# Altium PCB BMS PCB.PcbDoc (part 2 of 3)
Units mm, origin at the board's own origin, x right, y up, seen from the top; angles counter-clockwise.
Board outline 105 x 42 mm, 6 copper layers (TOP, GND TOP, IN, GND IN, GND BOT, BOT), stack 1.517 mm thick; 241 components, 153 nets, 670 pads, 889 vias.
Unrouted connection lines stored in the file: 76.
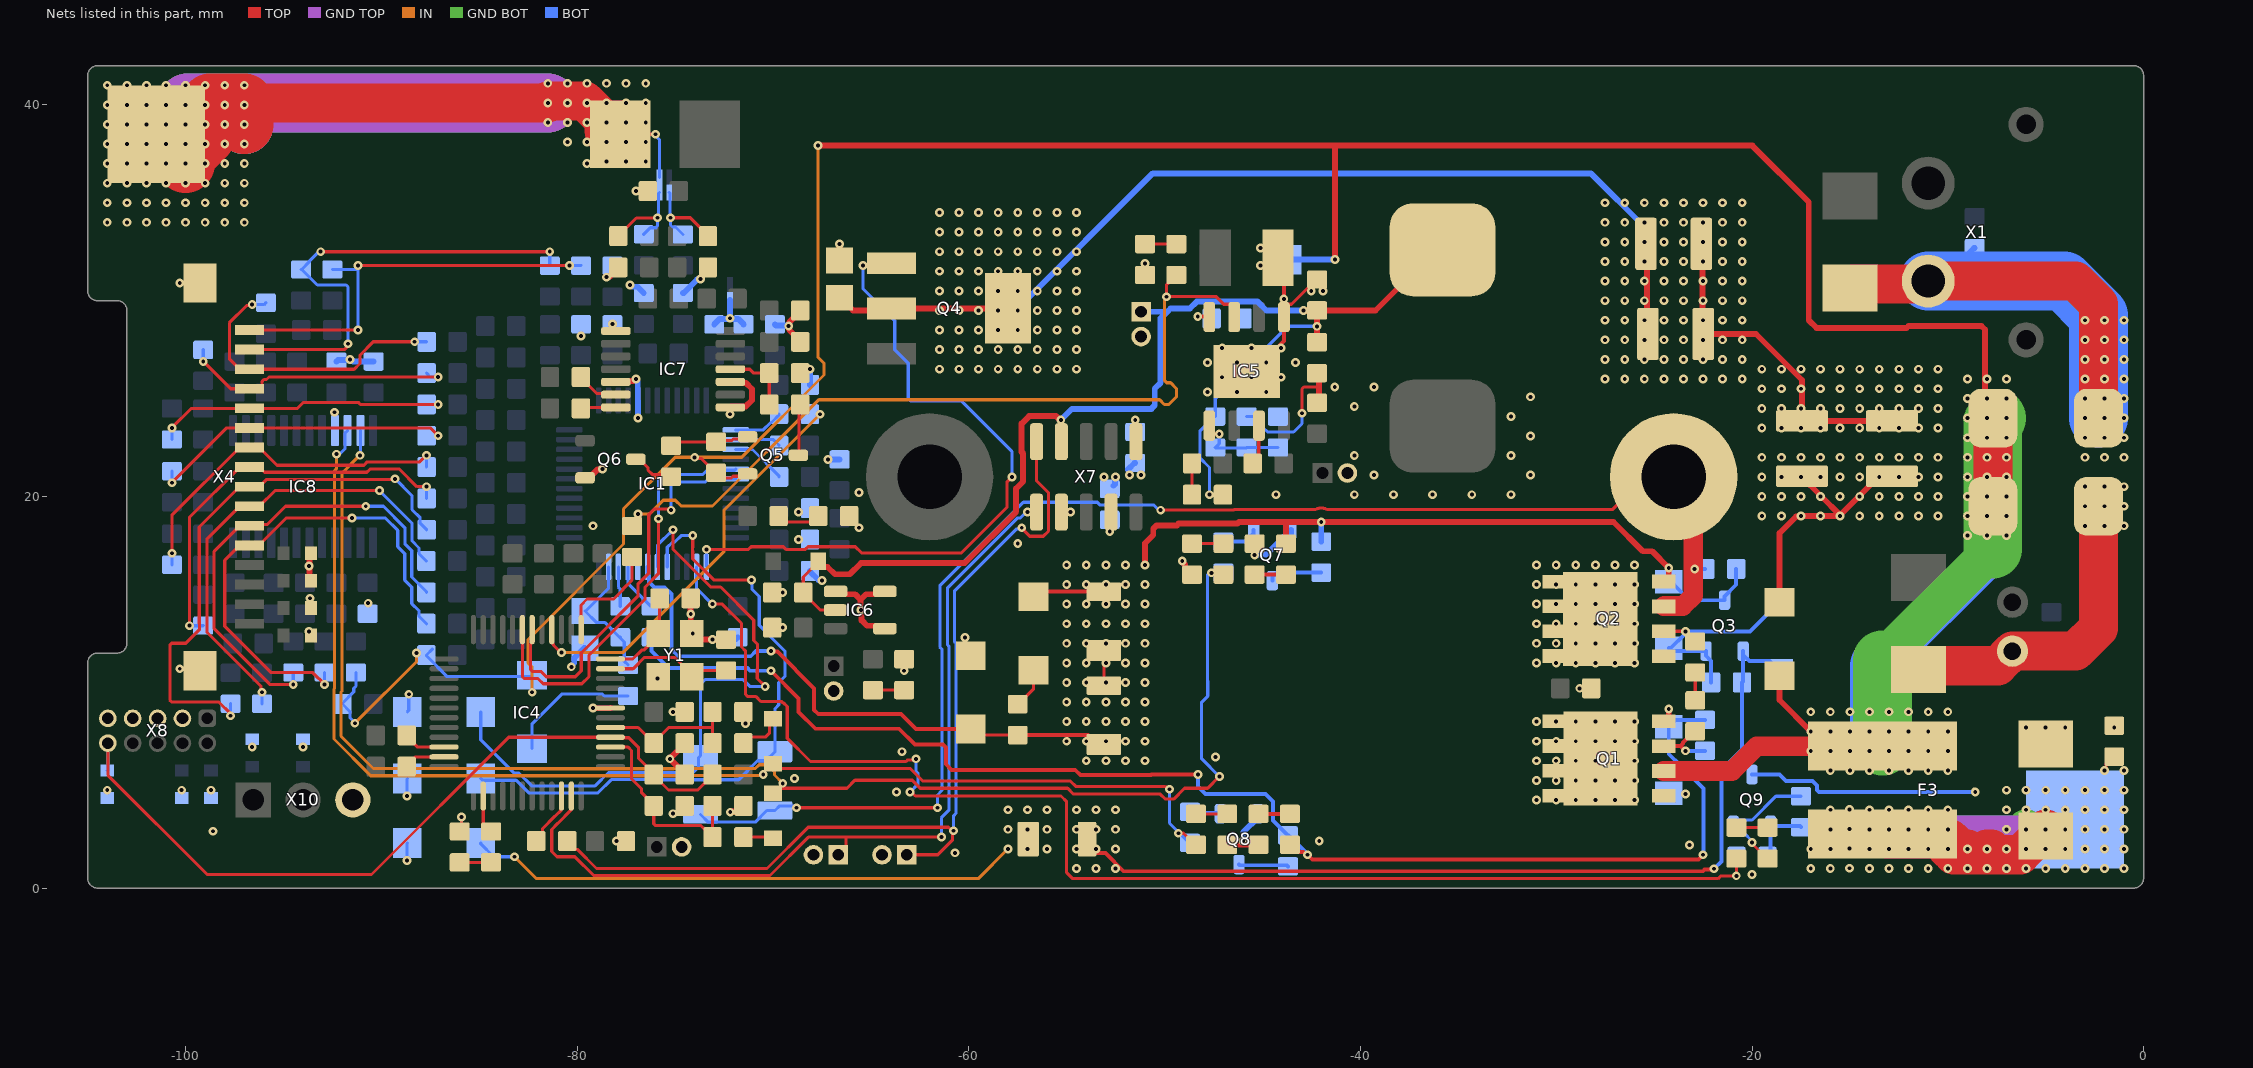
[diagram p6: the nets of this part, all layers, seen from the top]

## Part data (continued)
Y1: "Crystal oscillator 40MHz SMD 12pF 40R 10ppm", Frequency=40MHz, Manufacturer=JGHC

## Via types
v1: diameter 0.45, hole 0.2, TOP to BOT, tented both sides, 886 vias
v2: diameter 0.45/0.45/0.45/0.45/0.45/0 (per signal layer), hole 0.2, TOP to BOT, tented both sides, 3 vias

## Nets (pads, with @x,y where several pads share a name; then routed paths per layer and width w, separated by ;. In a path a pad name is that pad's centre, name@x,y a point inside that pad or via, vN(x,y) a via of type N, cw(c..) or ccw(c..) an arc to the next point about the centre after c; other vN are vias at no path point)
5V1: C41.2 C44.2 C45.2 D6.K IC6.2 L2.2 R63.2 R66.2 X7.4 X12.1 | length 67.2
  TOP w0.16: D6.K@-67.695,16.7 -67.695,16.65 -68.455,15.89 C45.2@-68.455,15.1 -68.455,15.06 -67.595,14.2 IC6.2@-66.8,14.2 ; v1(-47.705,20.09) R66.2@-47.02,20.09
  TOP w0.3: D6.K@-67.695,16.65 -67.445,16.4 -67.213,16.4 -66.838,16.025 -66.075,16.025 -65.5,16.6 -60.207,16.6 -57.58,19.227 -57.58,20.407 -57.225,20.762 -57.225,22.203 -57.3,22.278 -57.3,23.718 -56.918,24.1 -55.541,24.1 -55.354,23.913 v1@-55.313,23.913 ; v1(-55.3,23.9) -55.285,23.885 -55.285,22.815 X7.4@-55.27,22.8 ; v1(-42.9,29.5) C44.2@-42.21,29.5 ; C41.2@-42.21,27.621 C41.2@-42.21,27.88 v1(-42.21,28.69) C44.2@-42.21,29.5 ; L2.2@-36.918,33.698 L2.2@-35.81,32.59 -36.135,32.59 -39.225,29.5 C44.2@-42.21,29.5
  BOT w0.16: v1(-47.705,20.09) -47.71,20.095 -47.71,21.479 -48.2,21.969 -48.2,23.33 -47.45,24.08 R63.2@-47.41,24.08 -47.41,24.99 -43.71,28.69 v1(-42.21,28.69)
  BOT w0.3: v1(-55.3,23.9) -54.725,24.475 -50.676,24.475 -50.5,24.651 -50.5,25.513 -50.2,25.813 -50.2,29.1 -49.865,29.435 ; X12.1@-51.2,29.435 -49.865,29.435 ; v1(-42.9,29.5) -44.8,29.5 -45.25,29.95 -48.358,29.95 -48.708,29.6 -49.7,29.6 -49.865,29.435
ALRT: IC4.16 R31.2 | length 20.9
  TOP w0.16: IC4.16@-81.3,13.2 -81.279,13.179 -81.279,12.534 -81.215,12.47 -81.215,12.413 -80.827,12.025 v1(-80.8,12.025)
  IN w0.16: v1(-80.8,12.025) -77.669,12.025 -72.495,17.199 -72.495,19.305 v1(-67.6,24.2)
BAT: C7.1 C9.2 IC1.47 R19.2 | length 6.7
  BOT w0.16: IC1.47@-78.4,16.4 -78.4,15.306 -79.558,14.148 C9.2@-79.6,14.148 -79.024,13.572 -78.602,13.572 C7.1@-77.84,12.81 ; C7.1@-77.8,12.81 C7.1@-77.84,12.81 ; R19.2@-77.4,11.39 -77.6,11.59 -77.6,12.57 C7.1@-77.84,12.81
"BAT FG": IC7.4 R69.1 R72.2 | length 3.7
  TOP w0.16: IC7.4@-72.175,26.5 -71.185,26.5 -70.985,26.3 R72.2@-70.19,26.3 R69.1@-70.19,24.7
BAT+: C3.1 D7.A D13.A D16.A D29.A F1.1 F2.1 F3.2 Q1.S Q5.S R2.1 R10.1 R68.2 R79.1 R80.1 | length 195.1
  TOP w0.16: v1(-74,22) -73.945,21.945 -73.675,21.945 -72.94,21.21 R68.2@-72.9,21.21 -72.64,20.95 -72.12,20.95 -72.04,21.03 -71.42,21.03 Q5.S@-71.3,21.15
  TOP w0.2: Q1.S@-24.5,7.25 -23.66,7.25 ; v1(-23.39,7.01) -23.42,7.01 -23.66,7.25 ; C3.1@-22.9,8.01 -22.94,8.01 -23.519,7.431 -23.519,7.391 -23.66,7.25
  TOP w0.3: v1(-67.7,37.917) -41.3,37.917 ; v1(-41.3,32.1) -41.3,37.917 ; D13.A@-18.6,10.85 -18.6,9.6 v1(-17,8) ; v1(-8,25) -8.1,25.1 -8.1,28.524 -8.276,28.7 -12.012,28.7 -12.112,28.6 -16.7,28.6 -17.1,29 -17.1,35.034 -19.983,37.917 -41.3,37.917
  TOP w1: Q1.S@-24.5,5.98 -21.02,5.98 -19.75,7.25 F3.2@-13.335,7.25
  TOP w2: F2.1@-7.7,19.5 -7.7,23.8 F1.1@-7.5,24
  GND BOT w2: -13.335,11.665 -7.7,17.3
  GND BOT w3: -13.335,7.25 -13.335,11.665 ; -7.7,17.3 -7.7,23.8 -7.5,24
  IN w0.16: v1(-91.357,8.416) -88.2,11.573 v1(-88.2,12) ; v1(-82.3,10) -82.3,11.286 -82.505,11.491 -82.505,12.698 -77.634,17.569 -77.634,19.363 -74.997,22 v1(-74,22) -71.6,22 -67.395,26.205 -67.395,26.801 -67.7,27.106 v1(-67.7,37.917)
  BOT w0.16: v1(-91.357,8.416) -91.357,8.457 -91.609,8.709 -91.609,9.019 R79.1@-91.99,9.4 -91.99,9.448 -91.413,10.024 -91.413,10.201 -91.3,10.314 R80.1@-91.3,11.01 ; R10.1@-87.402,12.198 R10.1@-87.7,11.9 -87.7,11.86 -86.64,10.8 -82.375,10.8 D16.A@-82.3,10.875 v1(-82.3,10)
  BOT w0.2: v1(-23.39,7.01) R2.1@-22.4,7.01
  BOT w0.3: D29.A@-43.735,32.09 -43.725,32.1 v1(-41.3,32.1)
  BOT w2: -13.5,11.336 -7.7,17.136 -7.7,23.7 v1(-8,24)
  BOT w3: -13.5,7.415 -13.5,11.336
  other v1: -23.4,4.8 -16,6 -15,6 -14,6 -13,6 -12,6 -11,6 -10,6 -17,7 -16,7 -15,7 -14,7 -13,7 -12,7 -11,7 -10,7 -16,8 -15,8 -14,8 -13,8 -12,8 -11,8 -10,8 -17,9 -16,9 -15,9 -14,9 -13,9 -12,9 -11,9 -10,9 -9,18 -8,18 -7,18 -9,19 -8,19 -7,19 -9,20 -8,20 -7,20 -9,21 -8,21 -7,21 -9,22 -8,22 -7,22 -9,23 -8,23 -7,23 -9,24 -7,24 -9,25 -7,25 -9,26 -8,26 -7,26
"BAT+ C": C52.2 D32.K F3.1 X3.1 | length 36.1
  TOP w0.16: C52.2@-1.5,6.71 -1.532,6.71 -1.921,6.321 v1@-1.921,6.157 ; v1@-1.921,6.157 -1.921,6.079 v1(-2,6) -2,6.078 v1@-1.921,6.157
  TOP w2: F3.1@-13.335,2.75 -13.085,2.5 -9.864,2.5 -9.363,2 v1(-9,2) ; v1(-10,2) -9.7,1.7 -6.3,1.7 v1(-5,3) ; v1(-8,2) -7.768,2
  GND TOP w2: -13.3,2.7 -5.3,2.7 v1(-5,3)
  GND BOT w2: -13.3,2.7 -6.3,2.7 v1(-6,3)
  BOT w2: -13.3,2.7 -5,2.7 v1(-5,3)
  other v1: -17,1 -16,1 -14,1 -13,1 -12,1 -11,1 -10,1 -9,1 -8,1 -7,1 -6,1 -5,1 -4,1 -3,1 -2,1 -1,1 -15.019,1.013 -17,2 -16,2 -15.019,2.013 -14,2 -13,2 -12,2 -11,2 -7,2 -6,2 -5,2 -4,2 -3,2 -2,2 -1,2 -16,3 -14,3 -13,3 -12,3 -11,3 -10,3 -7,3 -4,3 -3,3 -2,3 -1,3 -15.019,3.013 -16,4 -14,4 -13,4 -12,4 -11,4 -10,4 -7,4 -6,4 -5,4 -4,4 -3,4 -2,4 -1,4 -15.019,4.013 -7,5 -6,5 -5,5 -4,5 -3,5 -2,5 -1,5 -1,6
BREG: IC1.37 Q4.B | length 36.1
  TOP w0.16: v1(-73.4,17.3) -71.248,17.3 -71.118,17.43 -69.479,17.43 -69.344,17.295 -68.346,17.295 -68.211,17.43 -65.791,17.43 -65.471,17.11 -60.389,17.11 -58.04,19.459 -58.04,20.76 v1(-57.8,21) ; v1(-65.4,31.8) -64.04,31.8 Q4.B@-63.94,31.9
  BOT w0.16: IC1.37@-73.4,16.4 v1(-73.4,17.3) ; v1(-65.4,31.8) -65.4,30.6 -63.78,28.98 -63.78,27.494 -63.095,26.809 -63.095,24.999 -62.986,24.89 -60.389,24.89 -57.8,22.301 v1(-57.8,21)
C1: R33.1 R92.1 X4.1 | length 21.5
  TOP w0.16: X4.1@-96.737,28.5 -93.6,28.5 v1(-91.2,28.5) ; v1(-91.2,31.8) v1(-80.4,31.8)
  BOT w0.16: R92.1@-92.5,31.59 -92.49,31.6 v1@-91.2,31.6 ; v1(-91.2,28.5) v1@-91.2,31.6 ; v1(-91.2,31.8) v1@-91.2,31.6 ; v1(-80.4,31.8) -79.81,31.8 R33.1@-79.8,31.79
C2: R30.1 R91.1 X4.2 | length 24.7
  TOP w0.16: X4.2@-96.737,27.5 -91.9,27.5 -91.7,27.7 v1(-91.7,27.8) ; v1(-93.1,32.5) v1(-81.4,32.5)
  BOT w0.16: R91.1@-94.06,31.59 -93.27,30.8 -91.799,30.8 -91.705,30.706 -91.705,27.805 v1(-91.7,27.8) ; v1(-93.1,32.5) -93.155,32.445 -93.245,32.445 -93.679,32.011 -93.679,31.979 R91.1@-94.068,31.59 ; R30.1@-81.4,31.79 v1(-81.4,32.5) ; R91.1@-94.068,31.59 R91.1@-94.1,31.59 R91.1@-94.068,31.59
C3: R28.1 R90.1 X4.3 | length 15.3
  TOP w0.16: v1(-96.6,29.8) -96.655,29.745 -96.889,29.745 -97.767,28.866 -97.767,27.03 -97.237,26.5 X4.3@-96.737,26.5 -91.814,26.5 -91.809,26.495 -91.391,26.495 -91.095,26.791 -91.095,27.219 -90.414,27.9 v1(-88.3,27.9)
  BOT w0.16: v1(-96.6,29.8) -95.99,29.8 R90.1@-95.9,29.89 ; v1(-88.3,27.9) R28.1@-87.69,27.9
C4: R26.1 R89.1 X4.4 | length 14.2
  TOP w0.16: v1(-99.1,26.9) -97.7,25.5 -96.264,25.5 -96.094,25.67 -96.094,25.876 -96,25.97 -95.871,25.97 -95.741,26.1 v1(-87.1,26.1)
  BOT w0.16: v1(-99.1,26.9) R89.1@-99.1,27.49 ; R26.1@-87.69,26.3 -87.49,26.1 v1(-87.1,26.1)
C5: R25.1 R88.1 X4.5 | length 14.8
  TOP w0.16: v1(-100.7,23.5) -99.7,24.5 -94.281,24.5 -93.977,24.805 -91.18,24.805 -91.075,24.7 -89.5,24.7 v1(-87.1,24.7)
  BOT w0.16: R88.1@-100.7,22.91 v1(-100.7,23.5)
C6: R24.1 R87.1 X4.6 | length 15.5
  TOP w0.16: v1(-100.7,20.7) -97.9,23.5 X4.6@-96.737,23.5 -87.5,23.5 v1(-87.1,23.1)
  BOT w0.16: v1(-100.7,20.7) R87.1@-100.7,21.29
C7: R23.1 R86.1 X4.7 | length 18.2
  TOP w0.16: v1(-100.7,17.1) -100.7,19.037 -97.237,22.5 -96.237,22.5 -95.332,21.595 -90.891,21.595 -90.721,21.765 -88.035,21.765 v1(-87.7,22.1)
  BOT w0.16: R86.1@-100.7,16.51 v1(-100.7,17.1) ; v1(-87.7,22.1) -87.7,21.51 R23.1@-87.69,21.5
C8: R22.1 R85.1 X4.8 | length 20.1
  TOP w0.16: v1(-99.8,13.4) -99.8,18.937 X4.8@-97.237,21.5 ; X4.8@-96.737,21.5 -96.237,21.5 -96.067,21.33 -96.067,21.329 -95.973,21.235 -90.742,21.235 -90.572,21.405 -89.091,21.405 -88.186,20.5 v1(-87.7,20.5)
  BOT w0.16: v1(-99.8,13.4) -99.11,13.4 R85.1@-99.1,13.41 ; v1(-87.7,20.5) -87.7,19.91 R22.1@-87.69,19.9
C9: R21.1 R84.1 X4.9 | length 28
  TOP w0.16: v1(-97.7,8.8) -97.7,8.9 -98.3,9.5 -100.706,9.5 -100.805,9.599 -100.805,12.401 -100.706,12.5 -99.986,12.5 -99.295,13.191 -99.295,13.5 -99.3,13.505 -99.3,18.437 X4.9@-97.067,20.67 ; X4.9@-96.737,20.5 -96.237,20.5 -95.862,20.875 -89.325,20.875 v1(-89.3,20.9)
  BOT w0.16: v1(-97.7,8.8) R84.1@-97.7,9.41 ; v1(-89.3,20.9) -88.44,20.04 -88.44,19.329 -88.023,18.912 -88.023,18.633 R21.1@-87.69,18.3
C10: R20.1 R83.1 X4.10 | length 24
  TOP w0.16: v1(-96.1,10) -96.142,10.042 -96.142,10.296 -98.9,13.054 -98.9,17.837 -97.237,19.5 -96.237,19.5 -95.437,20.3 v1(-90.1,20.3)
  BOT w0.16: R83.1@-96.1,9.41 v1(-96.1,10) ; v1(-90.1,20.3) -88.44,18.64 -88.44,17.729 -88.081,17.37 -88.081,17.081 R20.1@-87.7,16.7
C11: R18.1 R82.1 X4.11 | length 24.7
  TOP w0.16: v1(-94.5,10.4) -95.7,10.4 -98.54,13.24 -98.54,17.197 -97.237,18.5 X4.11@-96.737,18.5 -96.678,18.559 -95.841,18.559 -94.9,19.5 v1(-90.8,19.5)
  BOT w0.16: v1(-94.5,10.4) R82.1@-94.5,11.01 ; v1(-90.8,19.5) -89.891,19.5 -88.8,18.409 -88.8,17.58 -88.45,17.23 -88.45,15.89 -87.7,15.14 R18.1@-87.7,15.1
C12: R14.1 R81.1 X4.12 | length 25.7
  TOP w0.16: v1(-92.9,10.4) -93.5,11 -95.633,11 -98,13.367 -98,16.737 -97.237,17.5 -96.237,17.5 -96.067,17.67 -96.067,17.697 -94.864,18.9 v1(-91.5,18.9)
  BOT w0.16: v1(-92.9,10.4) R81.1@-92.9,11.01 ; v1(-91.5,18.9) -89.8,18.9 -89.167,18.267 -89.167,17.438 -88.81,17.081 -88.81,15.728 -88.45,15.368 -88.45,14.529 -88.081,14.16 -88.081,13.881 R14.1@-87.7,13.5
"CAN RX": IC4.47 X7.1 X15.1 | length 44
  TOP w0.16: IC4.47@-80.3,4.7 -80.321,4.679 -80.321,3.968 -80.984,3.305 -80.989,3.305 -81.3,2.994 -81.3,1.869 -81.031,1.6 -80.12,1.6 -79.16,0.64 -70.155,0.64 -68.195,2.6 -66.3,2.6 ; X15.1@-66.265,1.7 -66.265,2.565 -66.3,2.6 ; v1(-61.4,2.6) -66.3,2.6
  BOT w0.16: v1(-61.4,2.6) -61.4,3.586 -61.015,3.971 -61.015,12.357 -61.095,12.437 -61.095,15.315 -57.505,18.905 -57.363,18.905 -57.068,19.2 v1(-57,19.2)
"CAN TX": R38.2 X7.2 X16.1 | length 48.1
  TOP w0.16: R38.2@-80.51,2.4 -80.51,2.368 -80.121,1.979 -79.99,1.979 -79.011,1 -70.304,1 -68.199,3.105 -61.034,3.105 -60.854,2.925 v1(-60.776,2.925) -60.826,2.875 -60.826,2.46 -61.586,1.7 X16.1@-63.165,1.7 ; v1(-57.296,18.4) -57.15,18.4 -57.15,18.231 -56.889,17.97 -56.191,17.97 -55.93,18.231 -55.93,20.189 -56.54,20.799 X7.2@-56.54,22.8
  BOT w0.16: v1(-60.776,2.925) -60.776,3.701 -60.655,3.822 -60.655,12.506 -60.735,12.586 -60.735,15.166 -57.557,18.345 -57.351,18.345 v1(-57.296,18.4)
CFETOFF: IC1.29 IC4.19 | length 21.9
  TOP w0.16: IC4.19@-82.8,13.2 -82.8,10.8 -82.705,10.705 -82.008,10.705 -81.738,10.435 -79.764,10.435 -79.4,10.799 -79.4,11.889 -76.54,14.749 -76.54,15.371 -75.84,16.071 v1(-75.84,18.86)
  BOT w0.16: v1(-75.84,18.86) -75.84,20.966 -75.687,21.119 -73.584,21.119 -73.383,21.32 -72.589,21.32 -72.569,21.34 -71.96,21.34 IC1.29@-71.9,21.4
CHG: IC1.45 R6.1 | length 2.5
  BOT w0.16: IC1.45@-77.4,16.4 -77.4,15.55 -76.24,14.39 R6.1@-76.2,14.39
COUT: D38.A D40.A IC8.22 R100.1 | length 64.8
  TOP w0.16: v1(-70.5,5.795) -70.5,5.9 -70.05,6.35 D38.A@-70,6.35 -69.75,6.1 -69.114,6.1 -69.109,6.105 -68.691,6.105 -68.686,6.1 -62.977,6.1 -62.337,5.46 -54.806,5.46 -54.541,5.195 -49.973,5.195 -49.826,5.048 v1(-49.747,5.048) ; v1(-49.3,2.8) -49.038,2.8 -48.448,2.21 D40.A@-48.4,2.21
  IN w0.16: v1(-92.3,22.16) -92.3,21.409 -92.395,21.314 -92.395,10.191 -92.422,10.164 -92.422,7.612 -90.544,5.735 -74.912,5.735 -74.902,5.745 -70.55,5.745 v1(-70.5,5.795)
  BOT w0.16: v1(-92.3,22.16) -92.294,22.166 -92.134,22.166 -91.85,22.45 -91.85,23.245 IC8.22@-91.725,23.37 ; v1(-49.747,5.048) -49.747,3.317 -48.74,2.31 R100.1@-48.7,2.31
"COUT MCU": C69.2 IC4.5 R93.1 R95.2 | length 7.5
  TOP w0.16: IC4.5@-78.3,8.2 -76.89,8.2 -76.511,7.821 -76.479,7.821 C69.2@-76.09,7.432 ; C69.2@-76.09,7.4 C69.2@-76.09,7.432 ; R93.1@-73.09,7.4 -73.09,8.2 ; R95.2@-73.09,9 -73.09,8.2 ; C69.2@-76.09,7.432 -76.09,7.44 -75.33,8.2 -73.09,8.2
CP1: C7.2 IC1.46 | length 2.1
  BOT w0.16: IC1.46@-77.9,16.4 -77.9,15.372 -77.8,15.272 C7.2@-77.8,14.39
"DCDC EN": D18.A IC5.3 R44.1 | length 42.2
  TOP w0.16: R44.1@-77.2,18.49 -76.9,18.79 v1(-76.9,19.1) ; D18.A@-49.4,31.31 -49.432,31.31 -49.821,30.921 -49.821,30.889 -49.9,30.81 v1(-49.9,30.2) -49.883,30.217 -47.387,30.217 -46.984,29.814 -46.66,29.814 -46.5,29.655 -46.5,29.217 IC5.3@-46.445,29.162
  IN w0.16: v1(-76.9,19.1) -76.314,19.1 -75.609,19.805 -74.991,19.805 -74.695,19.509 -73.091,19.509 -67.66,24.94 -50.254,24.94 -50.014,24.7 -49.786,24.7 -49.395,25.091 -49.395,25.509 -49.691,25.805 -49.891,25.805 -50,25.914 -50,30.1 v1(-49.9,30.2)
"DCDC EN MCU": IC4.13 R44.2 | length 5.6
  TOP w0.16: IC4.13@-79.8,13.2 -79.8,14.46 -79.5,14.76 -78.129,14.76 -77.665,15.224 -77.665,15.265 -77.2,15.729 R44.2@-77.2,16.91
DFETOFF: IC1.30 IC4.18 | length 20.4
  TOP w0.16: IC4.18@-82.3,13.2 -82.3,12.555 -82.385,12.47 -82.385,11.159 -82.291,11.065 -81.859,11.065 -81.589,10.795 -80.091,10.795 -79.795,11.091 -79.795,12.003 -76.9,14.898 -76.9,15.52 -76.345,16.075 -76.345,19.069 -76.049,19.365 -75.631,19.365 -75.621,19.355 -75.255,19.355 v1(-75.2,19.3)
  BOT w0.16: v1(-75.2,19.3) -75.2,20.646 -75.106,20.74 -73.454,20.74 -73.294,20.9 IC1.30@-71.9,20.9
DOUT: D37.A D39.A IC8.23 R98.1 | length 76.7
  TOP w0.16: D37.A@-69.725,5.075 -69.95,4.85 D37.A@-70,4.85 -69.88,4.85 -69.63,5.1 -69.114,5.1 -69.109,5.095 -68.691,5.095 -68.686,5.1 -66.222,5.1 -65.817,5.505 -62.891,5.505 -62.486,5.1 -54.955,5.1 -54.655,4.8 -50.214,4.8 -49.957,4.543 -49.538,4.543 -48.981,5.1 -48.606,5.1 -48.601,5.095 -47.805,5.095 v1(-47.2,5.7) ; D37.A@-69.63,5.17 -69.5,5.3 v1(-69.5,5.35) ; v1(-47.6,16.1) -47.09,16.1 D39.A@-47,16.01
  IN w0.16: v1(-91.1,22.1) -92.005,21.195 -92.005,10.072 -92.062,10.015 -92.062,7.762 -90.4,6.1 -82.733,6.1 -82.728,6.095 -75.061,6.095 -75.051,6.105 -70.905,6.105 -70.709,6.3 -70.291,6.3 -69.923,5.932 -69.923,5.773 v1(-69.5,5.35)
  BOT w0.16: v1(-91.1,22.1) -91.075,22.125 IC8.23@-91.075,23.37 ; v1(-47.2,5.7) -48.106,6.606 -48.106,9.494 -47.795,9.805 -47.795,10.579 -47.811,10.594 -47.811,16.016 -47.717,16.11 R98.1@-47,16.11
"DOUT MCU": C70.2 IC4.3 R94.1 R96.2 | length 10.3
  TOP w0.16: IC4.3@-78.3,7.2 -77.4,7.2 -77.226,7.025 -77.226,5.575 -76.709,5.059 -76.709,4.859 -76.09,4.24 -76.09,3.284 -75.996,3.19 -73.68,3.19 -73.511,3.021 -73.479,3.021 -73.09,2.632 R94.1@-73.09,2.6 R96.2@-73.09,4.2
DSG: D11.K IC1.43 R7.1 R8.1 | length 30
  TOP w0.16: D11.K@-59.9,8.125 -59.585,7.81 R7.1@-57.5,7.81
  TOP w0.2: v1(-70.1,12.1) -70.079,12.079 -69.779,12.079 -67.9,10.2 -67.9,9.1 -67.688,8.888 -63.457,8.888 -62.695,8.125 D11.K@-59.9,8.125 ; R7.1@-57.5,7.81 -53.915,7.81 -53.605,7.5 v1(-53,7.5)
  BOT w0.2: IC1.43@-76.4,16.4 -76.4,16 -76.34,15.94 -76.34,15.642 -76.058,15.36 -75.538,15.36 -75.19,15.012 -75.19,12.191 -74.839,11.84 -71.138,11.84 -70.878,12.1 v1(-70.1,12.1)
  other v1: -54,6.5 -53,6.5 -52,6.5 -51,6.5 -55,7.5 -54,7.5 -52,7.5 -51,7.5 -55,8.5 -54,8.5 -53,8.5 -52,8.5 -51,8.5
"FB 5V1": C42.1 IC5.5 R63.1 R65.2 | length 4.8
  TOP w0.16: IC5.5@-47.715,23.618 -47.715,23.4 -47.5,23.185 v1(-47.21,23.185)
  BOT w0.16: v1(-47.21,23.185) -47.21,22.7 R63.1@-47.41,22.5 -47.393,22.482 -45.828,22.482 C42.1@-45.81,22.5 R65.2@-44.21,22.5
FUSE: D44.A IC1.38 R106.2 | length 69
  TOP w0.16: v1(-73.1,14.5) -72.592,14.5 -71.61,13.518 -71.61,12.31 -71.4,12.1 -71.4,9.884 -71.306,9.79 -70.887,9.79 -70.622,9.525 -69.554,9.525 -69.4,9.4 -69.388,9.389 -69.27,9.271 -69.27,7.651 -68.084,6.465 -66.035,6.465 -66.031,6.461 -63.2,6.461 -63.117,6.545 -62.755,6.545 v1(-62.7,6.6) ; v1(-63,4.9) -62.922,4.9 -62.727,4.705 -55.294,4.705 -55.005,4.416 -55.005,0.791 -54.694,0.48 -21.732,0.48 -21.587,0.625 v1(-20.8,0.625) D44.A@-20.8,1.51
  BOT w0.16: IC1.38@-73.9,16.4 -73.9,15.3 v1(-73.1,14.5) ; v1(-63,4.9) -62.6,5.3 -62.6,5.861 -62.7,5.961 v1(-62.7,6.6) ; v1(-20.8,0.625) -20.79,0.635 R106.2@-20.79,1.6
G_CHG: D7.K D41.A Q1.G R2.2 R6.2 R99.2 | length 72.8
  TOP w0.2: v1(-70.1,11.1) -68.69,9.69 -68.69,8.99 -67.837,8.137 -63.555,8.137 -62.743,7.325 -61.307,7.325 -61.165,7.183 -61.165,6.322 -60.883,6.04 -54.565,6.04 -54.3,5.775 -50.7,5.775 -50.675,5.8 v1(-48.3,5.8) ; D41.A@-43.6,2.21 -43.23,1.84 -42.908,1.84 -42.768,1.7 v1(-42.7,1.7) -42.698,1.7 -42.458,1.46 -22.742,1.46 -22.502,1.7 v1(-22.5,1.7)
  TOP w0.3: Q1.G@-24.5,8.52 -24.25,8.77 v1(-24.25,9.15)
  BOT w0.2: R6.2@-76.2,12.81 -76.2,12.1 -75.34,11.24 -71.308,11.24 -71.168,11.1 v1(-70.1,11.1) ; v1(-48.3,5.8) -48.3,5.179 -47.921,4.8 -44.837,4.8 -44.459,4.422 -44.459,3.449 R99.2@-43.7,2.69 ; R99.2@-43.66,2.69 -42.7,1.73 v1(-42.7,1.7) ; v1(-24.25,9.15) D7.K@-24.25,8.25 ; v1(-22.5,1.7) -22.475,1.725 -22.475,5.082 -23.644,6.251 -23.656,6.251 -24.25,6.845 D7.K@-24.25,8.25 ; R2.2@-22.4,8.59 -23.91,8.59 D7.K@-24.25,8.25
  BOT w0.3: v1@-24.291,9.15 v1(-24.25,9.15)
G_DSG: D8.K D9.A D42.A Q2.G Q3.D R3.1 R4.2 R97.2 | length 41.9
  TOP w0.2: D9.A@-56.7,14.875 -56.435,15.14 R4.2@-53.1,15.14 ; Q2.G@-24.51,15.655 -24.5,15.655 Q2.G@-24.25,15.905
  TOP w0.3: v1(-51,16.5) -51,17.61 -50.58,18.03 -50.58,18.349 -50.404,18.525 -49.368,18.525 -49.283,18.61 -46.288,18.61 -46.198,18.7 -43.8,18.7 ; D42.A@-43.8,17.59 -43.8,18.7 ; Q2.G@-24.25,15.905 v1(-24.25,16.35) -25.1,17.2 -25.574,17.2 -27.074,18.7 v1(-42,18.7) -43.8,18.7
  BOT w0.2: v1(-24.25,16.35) D8.K@-24.25,15.65 -24.15,15.65 -23.2,14.7 Q3.D@-21.4,14.7 -21.4,14.9 -20.81,15.49 R3.1@-20.81,16.3
  BOT w0.3: R97.2@-42,17.69 v1(-42,18.7)
  other v1: -55,14.5 -54,14.5 -53,14.5 -52,14.5 -51,14.5 -55,15.5 -54,15.5 -53,15.5 -52,15.5 -51,15.5 -55,16.5 -54,16.5 -53,16.5 -52,16.5
GND_BMS: C1.1 C2.1 C9.1 C12.1 C13.1 C14.1 C15.1 C20.1 C24.1 C25.1 C26.1 C27.1 C29.2 C30.1 C35.1 C36.1 C37.1 C43.1 C44.1 C45.1 C46.1 C47.1 C48.1 C50.2 C51.1 C52.1 C53.1 C54.1 C55.1 C68.1 C69.1 C70.1 C71.1 C72.1 D1.A D2.A D3.A D4.A D5.A D11.A D12.A D14.A D15.A D32.A D33.K D34.K D35.K D36.K IC1.17 IC4.7 IC5.1 IC5.9 IC6.1 IC6.4 IC6.6 IC7.1 IC7.3 IC7.8 IC7.12 IC8.21 NT1.1 NT3.2 Q6.S Q7.S Q8.S Q9.S R1.1 R34.1 R35.1 R53.2 R59.2 R64.1 R65.1 R67.2 R72.1 R77.1 R78.1 R95.1 R96.1 R101.2 R102.2 R103.2 R104.2 R105.2 R107.1 R108.2 R109.1 X4.CASE X7.3 X8.3 X8.5 X8.7 X8.9 X9.1 X10.3 X11.2 X12.2 X13.2 X14.2 X15.2 X16.2 Y1.2 Y1.4 | length 170.1
  TOP w0.16: v1(-100.3,11.2) -99.363,11.2 X4.CASE@-99.263,11.1 ; v1(-100.3,30.9) X4.CASE@-99.263,30.9 ; R59.2@-86,2.89 -85.9,2.99 -85.9,3.6 -85.915,3.615 v1(-85.915,3.633) ; R1.1@-77.8,38.5 v1(-76,38.5) ; R105.2@-66.11,19 -66.11,18.952 -65.6,18.442 v1(-65.6,18.4) ; v1(-63.3,11.1) R67.2@-63.3,11.69 ; v1(-60.2,12.8) -60.2,12.175 D11.A@-59.9,11.875 ; R53.2@-51,31.31 v1(-51,31.9) ; IC5.1@-43.905,29.162 -43.905,29.6 -43.69,29.814 -43.516,29.814 -42.25,31.08 C44.1@-42.21,31.08 ; v1(-20,2.329) -20,2.278 -19.232,1.51 R108.2@-19.2,1.51
  TOP w0.2: IC5.9@-45.81,26.39 -45.465,26.39 -43.905,27.95 IC5.1@-43.905,29.162 ; C43.1@-44.21,32.842 C43.1@-44.21,32.19 -43.905,31.885 IC5.1@-43.905,29.6
  TOP w0.3: D34.K@-93.6,15.7 -93.671,15.771 -93.671,16.421 v2(-93.7,16.45) -93.671,16.479 -93.671,17.029 D33.K@-93.6,17.1 ; Q6.S@-79.6,20.95 -79.391,20.95 -78.97,21.371 -78.729,21.371 v1(-78.7,21.4) ; v1(-79.2,9.2) -79.185,9.185 -78.315,9.185 IC4.7@-78.3,9.2 ; v1(-78.5,31.2) -78.471,31.229 -78.331,31.229 -77.9,31.66 C50.2@-77.9,31.7 ; IC7.12@-78.025,25.85 -77.975,25.9 -77.141,25.9 -77.041,26 v1(-77,26) ; C37.1@-74.51,5.8 -74.51,5.84 -75.27,6.6 -74.51,7.36 C69.1@-74.51,7.4 ; C72.1@-74.21,14.8 -74.205,14.795 -74.205,14.005 v1(-74.2,14) -74.2,13.1 v1(-74.1,13) -73.79,12.69 v1(-73.095,12.69) C71.1@-72.4,12.69 ; v1(-72.2,24.2) -72.2,24.525 IC7.1@-72.175,24.55 -72.125,24.6 -71.389,24.6 -71.075,24.914 -71.075,25.486 -71.389,25.8 -72.125,25.8 IC7.3@-72.175,25.85 ; v1(-72.185,3.875) -72.156,3.904 -71.806,3.904 R96.1@-71.51,4.2 ; C47.1@-68.61,27.9 -68.61,27.94 -69.171,28.501 -69.171,28.671 v1(-69.2,28.7) -69.171,28.729 -69.171,28.899 -68.61,29.46 C48.1@-68.61,29.5 ; IC6.1@-66.8,15.15 -66.655,15.005 -65.805,15.005 -65.529,14.729 ; C13.1@-66.6,32.048 v1(-66.6,32.9) ; IC6.4@-64.29,13.25 -64.435,13.395 -65.195,13.395 -65.471,13.671 -65.471,14.171 v1(-65.5,14.2) -65.529,14.229 -65.529,14.729 ; IC6.6@-64.29,15.15 -64.435,15.005 -65.252,15.005 -65.529,14.729 ; v1(-49.1,16.7) -49.1,16.659 -48.96,16.519 -48.96,16.036 -48.924,16 -48.61,16 R101.2@-48.6,16.01 ; R102.2@-46.8,2.21 -46.19,2.21 ; v1(-46,2.4) -46.19,2.21 ; v1(-45.4,17) R104.2@-45.4,17.59 ; R103.2@-45.2,2.21 -46.19,2.21
  TOP w2: v1@-97,40.1 v1(-81.5,40.1) ; v1@-81.5,40.2 -79.607,40.2 R1.1@-78.135,38.728
  TOP w3: X9.1@-100.5,37.5 v1(-101,38) X9.1@-101.5,38.5 -100.5,39.5 -99.343,39.5 -98.743,40.1 -97,40.1 v1(-97,40) v1(-97,39) ; v1(-100,37) -100,37.382 -98.982,38.4 ; R1.1@-78.135,38.728 -77.85,38.728 -77.8,38.678 R1.1@-77.8,38.5
  GND TOP w3: -101.5,38.5 v1(-100,40) -99.9,40.1 v1@-97,40.1 ; v1(-97,39) v1(-97,40) v1@-97,40.1 ; v1(-81.5,40.1) v1@-97,40.1
  GND BOT w3: -101.5,38.5 v1(-100,40) -99.9,40.1 v1@-97,40.1 ; v1(-97,39) v1(-97,40) v1@-97,40.1 ; v1(-81.5,40.1) v1@-97,40.1
  BOT w0.16: v1(-88.7,1.4) -88.7,2.275 D12.A@-88.675,2.3 ; v1(-88.7,4.7) -88.7,5.575 D15.A@-88.675,5.6 ; D14.A@-88.675,9 -88.6,9.075 v1(-88.6,9.9) ; v1(-76,38.5) -76,38.422 -75.8,38.222 NT1.1@-75.8,36.3 ; v1(-20,2.329) -20,2.4 -20.421,2.821 -20.744,2.821 -20.95,3.027 Q9.S@-20.95,3.2 -20.95,3.268 -20.744,3.474 -19.997,3.474 -18.781,4.69 R107.1@-17.5,4.69
  BOT w0.3: C68.1@-92.3,26.89 -92.219,26.971 -91.629,26.971 v1(-91.6,27) -91.559,27 -91.449,26.89 R109.1@-90.4,26.89 ; v1(-80.3,11.3) -80.3,11.341 -80.148,11.492 -80.148,11.746 -79.642,12.252 C9.1@-79.6,12.252 ; v1(-77.3,30.8) -77.259,30.8 -77.169,30.71 -76.92,30.71 C29.2@-76.6,30.39 ; v1(-77,26) -77,25.959 -76.91,25.869 -76.91,24.91 IC1.17@-76.9,24.9 ; v1(-76.9,24) IC1.17@-76.9,24.9 ; C30.1@-74.6,30.39 -74.56,30.39 -73.878,31.071 -73.729,31.071 v1(-73.7,31.1) ; v1(-73.095,12.69) -73.066,12.719 -71.891,12.719 C12.1@-71.8,12.81 ; C20.1@-73,28.79 -72.719,29.071 -72.229,29.071 v1(-72.2,29.1) ; NT3.2@-72.2,30.025 v1(-72.2,29.1) ; C53.1@-71.5,28.79 -71.781,29.071 -72.171,29.071 v1(-72.2,29.1) ; C54.1@-69.9,28.79 -69.839,28.729 -69.229,28.729 v1(-69.2,28.7) ; C15.1@-68.11,16.2 -68.11,16.16 -67.679,15.729 -67.529,15.729 v1(-67.5,15.7) ; C24.1@-68.11,25.7 -68.105,25.705 -68.105,26.495 v1(-68.1,26.5) ; v1(-67.19,21.89) R34.1@-66.6,21.89 ; C1.1@-52.605,20.545 -52.529,20.621 -52.529,20.971 v1(-52.5,21) ; C2.1@-51.86,21.39 -51.54,21.71 C2.1@-51.5,21.71 ; v1(-46,2.4) -45.971,2.429 -45.971,2.87 -45.25,3.591 Q8.S@-45.25,3.8 ; v1(-45.4,17) -45.371,17.029 -44.821,17.029 -43.9,17.95 -43.691,17.95 -43.55,18.091 Q7.S@-43.55,18.3
  BOT w3: -101.5,38.5 v1(-100,40) -99.9,40.1 v1@-97,40.1 ; v1(-97,40) v1@-97,40.1 ; v1(-81.5,40.1) v1@-97,40.1
  other v1: -20,0.7 -60.7,1.8 -23.2,2.2 -78,2.4 -42.1,2.4 -98.6,2.9 -75.1,3.8 -63.7,4.9 -104,5 -100.2,5 -98.7,5 -68.9,5.6 -75.27,6.6 -47.4,6.7 -63.41,6.966 -96.6,7.2 -94,7.2 -6,8.2 -5,8.2 -4,8.2 -1.5,8.2 -71.4,8.4 -75.1,9 -28.8,10.2 -75.9,10.7 -69.5,13.3 -90.675,14.55 -69.5,15.1 -57.5,17.6 -68.7,17.8 -79.2,18.5 -68.7,19.2 -54.8,19.2 -44.31,20.09 -40.31,20.09 -38.31,20.09 -36.31,20.09 -34.31,20.09 -32.31,20.09 -65.6,20.2 -53.1,21 -39.31,21.09 -31.31,21.09 -51.8,21.1 -51.2,21.1 -40.31,22.09 -32.31,22.09 -31.31,23.09 -32.31,24.09 -92.4,24.3 -40.31,24.59 -31.31,25.09 -47.81,25.34 -46.31,25.34 -44.81,25.34 -41.31,25.59 -39.31,25.59 -47.06,26.09 -45.56,26.09 -44.06,26.09 -47.81,26.84 -46.31,26.84 -44.81,26.84 -43.31,26.84 -47.06,27.59 -45.56,27.59 -44.06,27.59 -79.8,28.2 -78.2,28.8 -43.91,30.09 -42.51,30.49 -41.91,30.49 -45.11,31.79 -45.11,32.69 -104,34 -103,34 -102,34 -101,34 -100,34 -99,34 -98,34 -97,34 -104,35 -103,35 -102,35 -101,35 -100,35 -99,35 -98,35 -97,35 -77,35.6 -104,36 -103,36 -102,36 -101,36 -100,36 -99,36 -98,36 -97,36 -104,37 -103,37 -102,37 -101,37 -99,37 -98,37 -97,37 -79.5,37 -78.5,37.1 -77.5,37.1 -76.5,37.1 -104,38 -103,38 -102,38 -100,38 -99,38 -98,38 -97,38 -80.5,38.1 -79.5,38.1 -78.5,38.1 -77.5,38.1 -76.5,38.1 -104,39 -103,39 -102,39 -101,39 -100,39 -99,39 -98,39 -81.5,39.1 -80.5,39.1 -79.5,39.1 -78.5,39.1 -77.5,39.1 -76.5,39.1 -104,40 -103,40 -102,40 -101,40 -99,40 -98,40 -80.5,40.1 -79.5,40.1 -78.5,40.1 -77.5,40.1 -76.5,40.1 -104,41 -103,41 -102,41 -101,41 -100,41 -99,41 -98,41 -97,41 -81.5,41.1 -80.5,41.1 -79.5,41.1 -78.5,41.1 -77.5,41.1 -76.5,41.1
  other v2: -93.7,13.1 -93.65,14.8
HFXIN: C71.2 IC4.11 Y1.1 | length 6.7
  TOP w0.16: IC4.11@-78.3,11.2 -77.146,11.2 -76.566,11.78 -75.03,11.78 -74.15,10.9 Y1.1@-74.15,10.8 -74.1,10.85 -73.84,11.11 C71.2@-72.4,11.11
HFXOUT: C72.2 IC4.12 Y1.3 | length 4.9
  TOP w0.16: IC4.12@-78.3,11.7 -77.155,11.7 -76.701,12.154 -76.596,12.154 -75.85,12.9 Y1.3@-75.85,13 -75.79,13.06 C72.2@-75.79,14.8
LD: D15.K IC1.41 R15.1 | length 33.1
  TOP w0.16: v1(-74.1,18) -74.1,17.384 -74.105,17.379 -74.105,17.221 -74.1,17.216 -74.1,16.803 -73.035,15.738 v1(-71.095,15.738)
  BOT w0.16: D15.K@-84.925,5.6 -84.831,5.506 -83.119,5.506 -82.474,4.86 -78.935,4.86 -78.255,5.54 -75.746,5.54 -75.741,5.535 -71.757,5.535 -70.792,6.5 -70.365,6.5 R15.1@-69.9,6.965 -69.9,9.159 -69.705,9.354 -69.705,10.498 -69.395,10.808 -69.395,12.109 -70.7,13.414 -70.7,14.894 -71.079,15.273 -71.079,15.721 v1(-71.095,15.738) ; IC1.41@-75.4,16.4 -75.4,17.406 -75.131,17.675 -75.01,17.675 -74.686,18 v1(-74.1,18)
"LED B": D17.A IC4.38 | length 2
  TOP w0.16: IC4.38@-84.8,4.7 -84.8,3.279 -84.411,2.89 D17.A@-84.4,2.89
NC44: IC1.44
NetC1_2: C1.2 X7.7 | length 1.6
  TOP w0.16: v1(-52.8,18.2) -52.765,18.235 -52.765,19.165 X7.7@-52.73,19.2
  BOT w0.16: v1(-52.8,18.2) C1.2@-52.8,18.81
NetC2_2: C2.2 X7.10 | length 1.7
  TOP w0.16: v1(-51.5,23.9) -51.48,23.88 -51.48,22.82 X7.10@-51.46,22.8
  BOT w0.3: C2.2@-51.5,23.29 v1(-51.5,23.9)
NetC3_2: C3.2 C4.1 | length 1.4
  TOP w0.2: C3.2@-22.9,9.59 C4.1@-22.9,11.01
NetC13_2: C13.2 Q4.C R16.1 R17.1 | length 55.7
  TOP w0.3: C13.2@-66.6,30.152 -66.558,30.152 -65.906,29.5 -64.04,29.5 Q4.C@-63.94,29.6 -61.5,29.6 -60.5,29.6 -59.5,29.6 -58.5,29.6 Q4.C@-58,29.6 Q4.C@-57.5,29.6 ; v1(-25.5,33) -25.365,32.865 -25.365,28.35 R17.1@-25.315,28.3
  BOT w0.3: v1@-57.5,29.6 -50.6,36.5 -28.23,36.5 -25.415,33.685 -25.415,32.9 -25.365,32.85 -25.365,28.35 -25.315,28.3
  other v1: -27.5,26 -26.5,26 -25.5,26 -24.5,26 -61.5,26.5 -60.5,26.5 -59.5,26.5 -58.5,26.5 -57.5,26.5 -56.5,26.5 -55.5,26.5 -54.5,26.5 -27.5,27 -26.5,27 -25.5,27 -24.5,27 -61.5,27.5 -60.5,27.5 -59.5,27.5 -58.5,27.5 -57.5,27.5 -56.5,27.5 -55.5,27.5 -54.5,27.5 -27.5,28 -26.5,28 -25.5,28 -24.5,28 -61.5,28.5 -60.5,28.5 -59.5,28.5 -58.5,28.5 -57.5,28.5 -56.5,28.5 -55.5,28.5 -54.5,28.5 -27.5,29 -26.5,29 -25.5,29 -24.5,29 -61.5,29.5 -60.5,29.5 -59.5,29.5 -58.5,29.5 -57.5,29.5 -56.5,29.5 -55.5,29.5 -54.5,29.5 -27.5,30 -26.5,30 -25.5,30 -24.5,30 -61.5,30.5 -60.5,30.5 -59.5,30.5 -58.5,30.5 -57.5,30.5 -56.5,30.5 -55.5,30.5 -54.5,30.5 -27.5,31 -26.5,31 -25.5,31 -24.5,31 -61.5,31.5 -60.5,31.5 -59.5,31.5 -58.5,31.5 -57.5,31.5 -56.5,31.5 -55.5,31.5 -54.5,31.5 -27.5,32 -26.5,32 -25.5,32 -24.5,32 -61.5,32.5 -60.5,32.5 -59.5,32.5 -58.5,32.5 -57.5,32.5 -56.5,32.5 -55.5,32.5 -54.5,32.5 -27.5,33 -26.5,33 -24.5,33 -61.5,33.5 -60.5,33.5 -59.5,33.5 -58.5,33.5 -57.5,33.5 -56.5,33.5 -55.5,33.5 -54.5,33.5 -27.5,34 -26.5,34 -25.5,34 -24.5,34 -61.5,34.5 -60.5,34.5 -59.5,34.5 -58.5,34.5 -57.5,34.5 -56.5,34.5 -55.5,34.5 -54.5,34.5 -27.5,35 -26.5,35 -25.5,35 -24.5,35
NetC38_2: C38.2 D27.K F1.2 X1.+ | length 37.1
  TOP w2: D27.K@-15.2,30.65 D27.K@-15,30.65 -14.8,30.85 -11.34,30.85 -11.19,31 X1.+@-11,31 -3.472,31 -2.3,29.828 F1.2@-2.3,24
  BOT w0.3: X1.+@-11,31 -10.541,31.459 -9.891,31.459 -8.665,32.685 C38.2@-8.625,32.685
  BOT w3: X1.+@-11,31 -4.057,31 -2.3,29.243 -2.3,24
  other v1: -3,22 -2,22 -1,22 -3,23 -2,23 -1,23 -3,24 -2,24 -1,24 -3,25 -2,25 -1,25 -3,26 -2,26 -1,26 -3,27 -2,27 -1,27 -3,28 -2,28 -1,28 -3,29 -2,29 -1,29
NetC39_2: C39.2 D28.K F2.2 X2.1 | length 18.7
  TOP w0.3: D28.K@-11.7,11.15 D28.K@-11.5,11.15
  TOP w2: D28.K@-11.5,11.15 -11.3,11.35 -7.45,11.35 X2.1@-6.7,12.1 -3.472,12.1 -2.3,13.272 F2.2@-2.3,19.5
  BOT w0.3: X2.1@-6.7,12.1 -6.495,12.305 -4.905,12.305 C39.2@-4.7,12.51
  other v1: -3,18.5 -2,18.5 -1,18.5 -3,19.5 -2,19.5 -1,19.5 -3,20.5 -2,20.5 -1,20.5
NetC40_1: C40.1 IC5.7 | length 2.1
  TOP w0.16: C40.1@-45.5,21.69 -45.19,22.001 -45.19,23.603 IC5.7@-45.175,23.618
NetC41_1: C41.1 C42.2 R62.2 | length 8
  TOP w0.16: v1(-42.98,24.249) -42.98,25.496 -42.886,25.59 -42.11,25.59 ; R62.2@-42.21,24.78 R62.2@-42.11,24.78 ; C41.1@-42.21,26.3 C41.1@-42.11,26.3
  TOP w0.3: R62.2@-42.11,24.78 -42.11,25.59 C41.1@-42.11,26.3
  BOT w0.16: C42.2@-45.81,24.08 -45.094,24.08 -45,23.986 -45,23.549 -44.741,23.29 -43.41,23.29 -42.98,23.72 -42.98,24.134 v1(-42.98,24.249)
NetD9_K: D9.K R7.2 | length 2.1
  TOP w0.16: R7.2@-57.5,9.39 -57.46,9.39 -56.7,10.15 D9.K@-56.7,11.125
NetD10_K: D10.K Q3.G R5.1 R9.2 | length 46.9
  TOP w0.2: R9.2@-53.96,2.5 -53.96,2.151 -53.59,1.781 -53.023,1.781 -52.102,0.86 -22.494,0.86 -22.416,0.937 -21.989,0.937 v1(-21.941,0.985)
  BOT w0.2: v1(-21.941,0.985) -21.56,1.366 -21.56,6.04 -20.51,7.09 R5.1@-20.51,10.5 -20.45,10.56 Q3.G@-20.45,11.916 ; Q3.G@-20.45,12.1 Q3.G@-20.45,11.916 ; D10.K@-18.6,11.1 -19.1,11.6 -20.134,11.6 Q3.G@-20.45,11.916
  other v1: -54.5,1 -53.5,1 -52.5,1 -54.5,2 -53.5,2 -52.5,2 -54.5,3 -53.5,3 -52.5,3 -54.5,4 -53.5,4 -52.5,4
NetD12_K: D12.K R9.1 | length 28.3
  IN w0.16: v1(-83.2,1.6) -82.08,0.48 -59.52,0.48 v1(-58,2)
  BOT w0.16: D12.K@-84.925,2.3 -84.925,2.265 -84.275,1.615 -84.196,1.615 -84.181,1.6 v1(-83.2,1.6)
  other v1: -57,2 -56,2 -58,3 -57,3 -56,3 -58,4 -57,4 -56,4
NetD13_K: D13.K R12.2 R13.2 | length 13.4
  TOP w0.3: D13.K@-18.6,14.6 -18.6,18.125 -17.754,18.971 -17.529,18.971 v1(-17.5,19) v1(-16.5,19) v1(-15.5,19) ; v1(-17.5,21) -17.455,21 -16.477,20.023 -15.5,19.045 v1(-15.5,19) ; R13.2@-12.848,21.028 -13.517,21.028 -14.523,20.023 -15.471,19.074 -15.471,19.029 v1(-15.5,19)
  other v1: -19.5,19 -18.5,19 -14.5,19 -13.5,19 -12.5,19 -11.5,19 -10.5,19 -19.5,20 -18.5,20 -17.5,20 -16.5,20 -15.5,20 -14.5,20 -13.5,20 -12.5,20 -11.5,20 -10.5,20 -19.5,21 -18.5,21 -16.5,21 -15.5,21 -14.5,21 -13.5,21 -12.5,21 -11.5,21 -10.5,21 -19.5,22 -18.5,22 -17.5,22 -16.5,22 -15.5,22 -14.5,22 -13.5,22 -12.5,22 -11.5,22 -10.5,22
NetD16_K: D16.K R19.1 | length 6.8
  BOT w0.16: D16.K@-82.3,7.125 -82.3,8.4 -80.795,9.905 -78.708,9.905 -78.613,9.81 R19.1@-77.4,9.81
NetD17_K: D17.K R59.1 | length 1.6
  TOP w0.16: R59.1@-86,1.31 D17.K@-84.4,1.31
NetD18_K: D18.K R53.1 | length 1.6
  TOP w0.16: R53.1@-51,32.89 D18.K@-49.4,32.89
NetD30_A: D30.A R66.1 | length 1.6
  TOP w0.16: R66.1@-48.6,20.09 D30.A@-48.6,21.69
NetD31_K: D31.K R67.1 | length 1.6
  TOP w0.16: D31.K@-64.9,10.11 R67.1@-63.3,10.11
NetD37_K: D37.K R94.2 | length 1.5
  TOP w0.16: R94.2@-71.51,2.6 -70.05,2.6 D37.K@-70,2.55
NetD38_K: D38.K R93.2 | length 2.4
  TOP w0.16: R93.2@-71.51,7.4 -71.204,7.706 -70.394,7.706 -70.17,7.93 -70.17,8.48 D38.K@-70,8.65
NetD39_K: D39.K R101.1 | length 1.6
  TOP w0.16: R101.1@-48.6,17.59 D39.K@-47,17.59
NetD40_K: D40.K R102.1 | length 1.6
  TOP w0.16: D40.K@-48.4,3.79 R102.1@-46.8,3.79
NetD41_K: D41.K R103.1 | length 1.6
  TOP w0.2: R103.1@-45.2,3.79 D41.K@-43.6,3.79
NetD42_K: D42.K R104.1 | length 1.6
  TOP w0.2: R104.1@-45.4,16.01 D42.K@-43.8,16.01
NetD43_K: D43.K R105.1 | length 2.3
  TOP w0.16: D43.K@-69.71,19 -69.405,18.695 -67.995,18.695 R105.1@-67.69,19
NetD44_K: D44.K R108.1 | length 1.6
  TOP w0.16: D44.K@-20.8,3.09 R108.1@-19.2,3.09
NetF3_3: F3.3 Q9.D | length 11.9
  BOT w0.2: Q9.D@-20,5.8 -18.6,5.8 -18.26,5.46 -16.921,5.46 -16.69,5.229 -16.69,5.017 -16.573,4.9 v1(-8.6,4.9)
NetIC1_25: IC1.25 R31.1 | length 2.6
  BOT w0.16: IC1.25@-71.9,23.4 -70.49,23.4 -70.111,23.779 -70.079,23.779 -69.69,24.168 R31.1@-69.69,24.2
NetIC1_26: IC1.26 R29.1 | length 2.3
  BOT w0.16: IC1.26@-71.9,22.9 -69.99,22.9 R29.1@-69.69,22.6
NetIC1_27: IC1.27 R27.1 | length 2.8
  BOT w0.16: IC1.27@-71.9,22.4 -71.05,22.4 -69.69,21.04 R27.1@-69.69,21
NetIC4_34: IC4.34 R49.1 | length 2.2
  TOP w0.16: R49.1@-88.71,7.8 -88.71,7.767 -88.143,7.2 IC4.34@-86.8,7.2
NetIC4_35: IC4.35 R50.1 | length 2.1
  TOP w0.16: R50.1@-88.71,6.2 -88.71,6.232 -88.242,6.7 IC4.35@-86.8,6.7
NetIC4_46: IC4.46 R38.1 | length 2.8
  TOP w0.16: R38.1@-82.09,2.4 -81.763,2.727 -81.763,3.04 -81.138,3.665 -81.133,3.665 -80.821,3.977 -80.821,4.679 IC4.46@-80.8,4.7
NetIC5_4: IC5.4 R64.2 | length 1.4
  TOP w0.2: v1(-48.305,29.19) -47.743,29.19 IC5.4@-47.715,29.162
  BOT w0.2: v1(-48.305,29.19) -47.62,29.19 -47.61,29.18 -47.6,29.17 R64.2@-47.6,29.09
NetIC7_13: IC7.13 R73.1 | length 2.2
  TOP w0.16: R73.1@-79.81,26.1 -79.81,26.06 -79.015,25.265 -78.09,25.265 IC7.13@-78.025,25.2
NetIC7_14: IC7.14 R71.1 | length 1.8
  TOP w0.16: R71.1@-79.81,24.5 -79.76,24.55 IC7.14@-78.025,24.55
NetNT1_2: NT1.2 R36.1 R74.1 | length 5.1
  TOP w0.16: R74.1@-77.9,33.3 -77.9,33.332 -77.511,33.721 -77.479,33.721 -76.978,34.222 -75.908,34.222 v1(-75.897,34.233)
  BOT w0.16: R36.1@-76.6,33.39 -76.265,33.725 -75.991,33.725 -75.897,33.819 v1(-75.897,34.233) ; v1@-75.9,34.2 -75.849,34.251 -75.849,35.476 NT1.2@-75.8,35.525
NetNT2_2: NT2.2 R37.1 R75.1 | length 4.8
  TOP w0.16: v1(-75.235,34.235) -74.223,34.235 -73.718,33.73 -73.32,33.332 R75.1@-73.32,33.3
  BOT w0.16: NT2.2@-75.3,35.525 -75.267,35.492 -75.267,34.268 v1(-75.235,34.235) -75.235,33.864 -75.133,33.761 -74.981,33.761 R37.1@-74.6,33.38
NetQ1_D: Q1.D Q2.D
  other v1: -31,4.5 -30,4.5 -29,4.5 -28,4.5 -27,4.5 -26,4.5 -31,5.5 -30,5.5 -29,5.5 -28,5.5 -27,5.5 -26,5.5 -31,6.5 -30,6.5 -29,6.5 -28,6.5 -27,6.5 -26,6.5 -31,7.5 -30,7.5 -29,7.5 -28,7.5 -27,7.5 -26,7.5 -31,8.5 -30,8.5 -29,8.5 -28,8.5 -27,8.5 -26,8.5 -31,11.5 -30,11.5 -29,11.5 -28,11.5 -27,11.5 -26,11.5 -31,12.5 -30,12.5 -29,12.5 -28,12.5 -27,12.5 -26,12.5 -31,13.5 -30,13.5 -29,13.5 -28,13.5 -27,13.5 -26,13.5 -31,14.5 -30,14.5 -29,14.5 -28,14.5 -27,14.5 -26,14.5 -31,15.5 -30,15.5 -29,15.5 -28,15.5 -27,15.5 -26,15.5 -31,16.5 -30,16.5 -29,16.5 -28,16.5 -27,16.5 -26,16.5
NetQ5_D: Q5.D R69.2 | length 2.7
  TOP w0.16: Q5.D@-68.7,22.1 -68.666,22.1 -68.666,24.644 R69.2@-68.61,24.7
NetQ5_G: Q5.G R68.1 R70.2 | length 4.1
  TOP w0.16: R70.2@-75.2,22.59 -75,22.79 R68.1@-72.9,22.79 -72.84,22.85 -72.12,22.85 -72.04,22.93 -71.42,22.93 Q5.G@-71.3,23.05
NetQ6_D: Q6.D R70.1 | length 2.2
  TOP w0.16: Q6.D@-77,21.9 -76.816,21.9 -76.385,21.469 -76.385,21.345 -76.15,21.11 -75.3,21.11 R70.1@-75.2,21.01
NetQ7_D: Q7.D R97.1 | length 2.8
  BOT w0.2: Q7.D@-44.5,15.7 -44.5,15.884 -44.312,16.072 -44.128,16.072 -44.09,16.11 R97.1@-42,16.11
NetQ7_G: Q7.G R98.2 | length 1.9
  BOT w0.2: R98.2@-47,17.69 -45.876,17.69 -45.45,18.116 Q7.G@-45.45,18.3
NetQ8_D: Q8.D R99.1 | length 2.5
  BOT w0.2: Q8.D@-46.2,1.2 -46.166,1.166 -43.756,1.166 R99.1@-43.7,1.11
NetQ8_G: Q8.G R100.2 | length 1.6
  BOT w0.2: R100.2@-48.7,3.89 -48.644,3.834 -47.184,3.834 Q8.G@-47.15,3.8
NetQ9_G: Q9.G R106.1 R107.2 | length 3.3
  BOT w0.2: R106.1@-19.21,1.6 -19.05,1.76 Q9.G@-19.05,3.2 -19.016,3.166 -17.556,3.166 R107.2@-17.5,3.11
NetR4_1: R4.1 R8.2 | length 1.8
  TOP w0.16: R8.2@-53.1,10.34 R4.1@-53.1,12.135
  other v1: -55,9.5 -54,9.5 -53,9.5 -52,9.5 -51,9.5 -55,10.5 -54,10.5 -53,10.5 -52,10.5 -51,10.5 -55,11.5 -54,11.5 -53,11.5 -52,11.5 -51,11.5 -55,12.5 -54,12.5 -53,12.5 -52,12.5 -51,12.5 -55,13.5 -54,13.5 -53,13.5 -52,13.5 -51,13.5
NetR12_1: R12.1 R13.1 R16.2 R17.2 | length 17.4
  TOP w0.3: v1(-22.5,33) -22.535,32.965 -22.535,28.35 R17.2@-22.485,28.3 -19.8,28.3 -17.448,25.948 R12.1@-17.448,23.859 R13.1@-12.848,23.858
  other v1: -19.5,23.5 -18.5,23.5 -17.5,23.5 -16.5,23.5 -15.5,23.5 -14.5,23.5 -13.5,23.5 -12.5,23.5 -11.5,23.5 -10.5,23.5 -19.5,24.5 -18.5,24.5 -17.5,24.5 -16.5,24.5 -15.5,24.5 -14.5,24.5 -13.5,24.5 -12.5,24.5 -11.5,24.5 -10.5,24.5 -19.5,25.5 -18.5,25.5 -17.5,25.5 -16.5,25.5 -15.5,25.5 -14.5,25.5 -13.5,25.5 -12.5,25.5 -11.5,25.5 -10.5,25.5 -23.5,26 -22.5,26 -21.5,26 -20.5,26 -19.5,26.5 -18.5,26.5 -17.5,26.5 -16.5,26.5 -15.5,26.5 -14.5,26.5 -13.5,26.5 -12.5,26.5 -11.5,26.5 -10.5,26.5 -23.5,27 -22.5,27 -21.5,27 -20.5,27 -23.5,28 -22.5,28 -21.5,28 -20.5,28 -23.5,29 -22.5,29 -21.5,29 -20.5,29 -23.5,30 -22.5,30 -21.5,30 -20.5,30 -23.5,31 -22.5,31 -21.5,31 -20.5,31 -23.5,32 -22.5,32 -21.5,32 -20.5,32 -23.5,33 -21.5,33 -20.5,33 -23.5,34 -22.5,34 -21.5,34 -20.5,34 -23.5,35 -22.5,35 -21.5,35 -20.5,35
nRST: C37.2 D3.K IC4.4 R52.1 X8.10 | length 40.8
  TOP w0.16: X8.10@-103.97,7.4 -103.97,5.77 -98.895,0.695 -90.507,0.695 -83.502,7.7 IC4.4@-78.3,7.7 -78.279,7.679 -77.37,7.679 -76.866,7.174 -76.866,6.615 -76.09,5.84 C37.2@-76.09,5.8 -76.09,5.76 -75.34,5.01 -73.84,5.01 -73.09,5.76 R52.1@-73.09,5.8
  BOT w0.16: D3.K@-104,6 -103.97,6.03 X8.10@-103.97,7.4
PACK: D14.K IC1.42 R11.1 | length 34.2
  TOP w0.16: v1(-75.1,18.3) -75.1,17.293 -73.184,15.378 -72.678,15.378 -70.985,13.685 -70.985,12.646 -70.8,12.461 -70.8,11.184 -70.805,11.179 -70.805,11.1 -70.805,10.705 v1(-70.4,10.3)
  BOT w0.16: D14.K@-84.925,9 -84.925,7.576 -83.215,5.866 -82.97,5.866 -82.324,5.22 -79.084,5.22 -78.404,5.9 -75.597,5.9 -75.592,5.895 -74.085,5.895 -73.8,6.18 -73.8,6.665 R11.1@-73.7,6.765 -73.7,10.406 -73.446,10.66 -71.549,10.66 -71.189,10.3 v1(-70.4,10.3) ; IC1.42@-75.9,16.4 -75.9,17.509 -75.549,17.86 -75.54,17.86 v1(-75.1,18.3)
PACK+: C4.2 D8.A D10.A MH1.1 Q2.S Q3.S R3.2 R5.2 R11.2 R15.2 | length 85.2
  TOP w0.16: v1(-68.8,4.1) v1(-61.6,4.1) ; v1(-50.2,19.3) -46.551,19.3 -46.489,19.3 -46.459,19.33 -42.316,19.33 cw(c-42,18.7) -41.684,19.33 -27.133,19.33 -26.676,19.787 -25.213,19.787 MH1.1@-24,21
  TOP w0.2: Q2.S@-24.51,13.115 -23.465,13.115 -22.94,12.59 C4.2@-22.9,12.59
  TOP w1: Q2.S@-24.51,14.385 -24.49,14.405 -23.537,14.405 -23,14.942 -23,20 MH1.1@-24,21
  BOT w0.16: R11.2@-73.7,3.76 -73.31,3.37 -70.905,3.37 -70.315,3.96 R15.2@-69.9,3.96 -69.66,4.2 -68.894,4.2 -68.8,4.106 v1(-68.8,4.1) ; v1(-61.6,4.1) -61.6,4.755 -61.375,4.98 -61.375,12.207 -61.475,12.307 -61.475,15.444 -57.214,19.705 -53.436,19.705 -53.291,19.56 -50.538,19.56 -50.278,19.3 v1(-50.2,19.3)
  BOT w0.2: v1(-22.927,16.3) R3.2@-22.39,16.3 ; R5.2@-22.09,10.5 -22.09,11.607 -22.35,11.867 Q3.S@-22.35,12.1 -24.1,12.1 D8.A@-24.25,12.25 -24.15,12.25 -23.448,12.952 -23.448,13.052 v1(-23.4,13.1) -20.1,13.1 -18.7,14.5 D10.A@-18.6,14.5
